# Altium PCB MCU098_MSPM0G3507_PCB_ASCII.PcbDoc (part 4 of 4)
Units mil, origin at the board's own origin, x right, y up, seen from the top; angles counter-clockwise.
Board outline 2310.03 x 4205.03 mil, 4 copper layers (Top Layer, VCC Layer, GND Layer, Bottom Layer), stack 62.4 mil thick; 260 components, 182 nets, 835 pads, 237 vias.
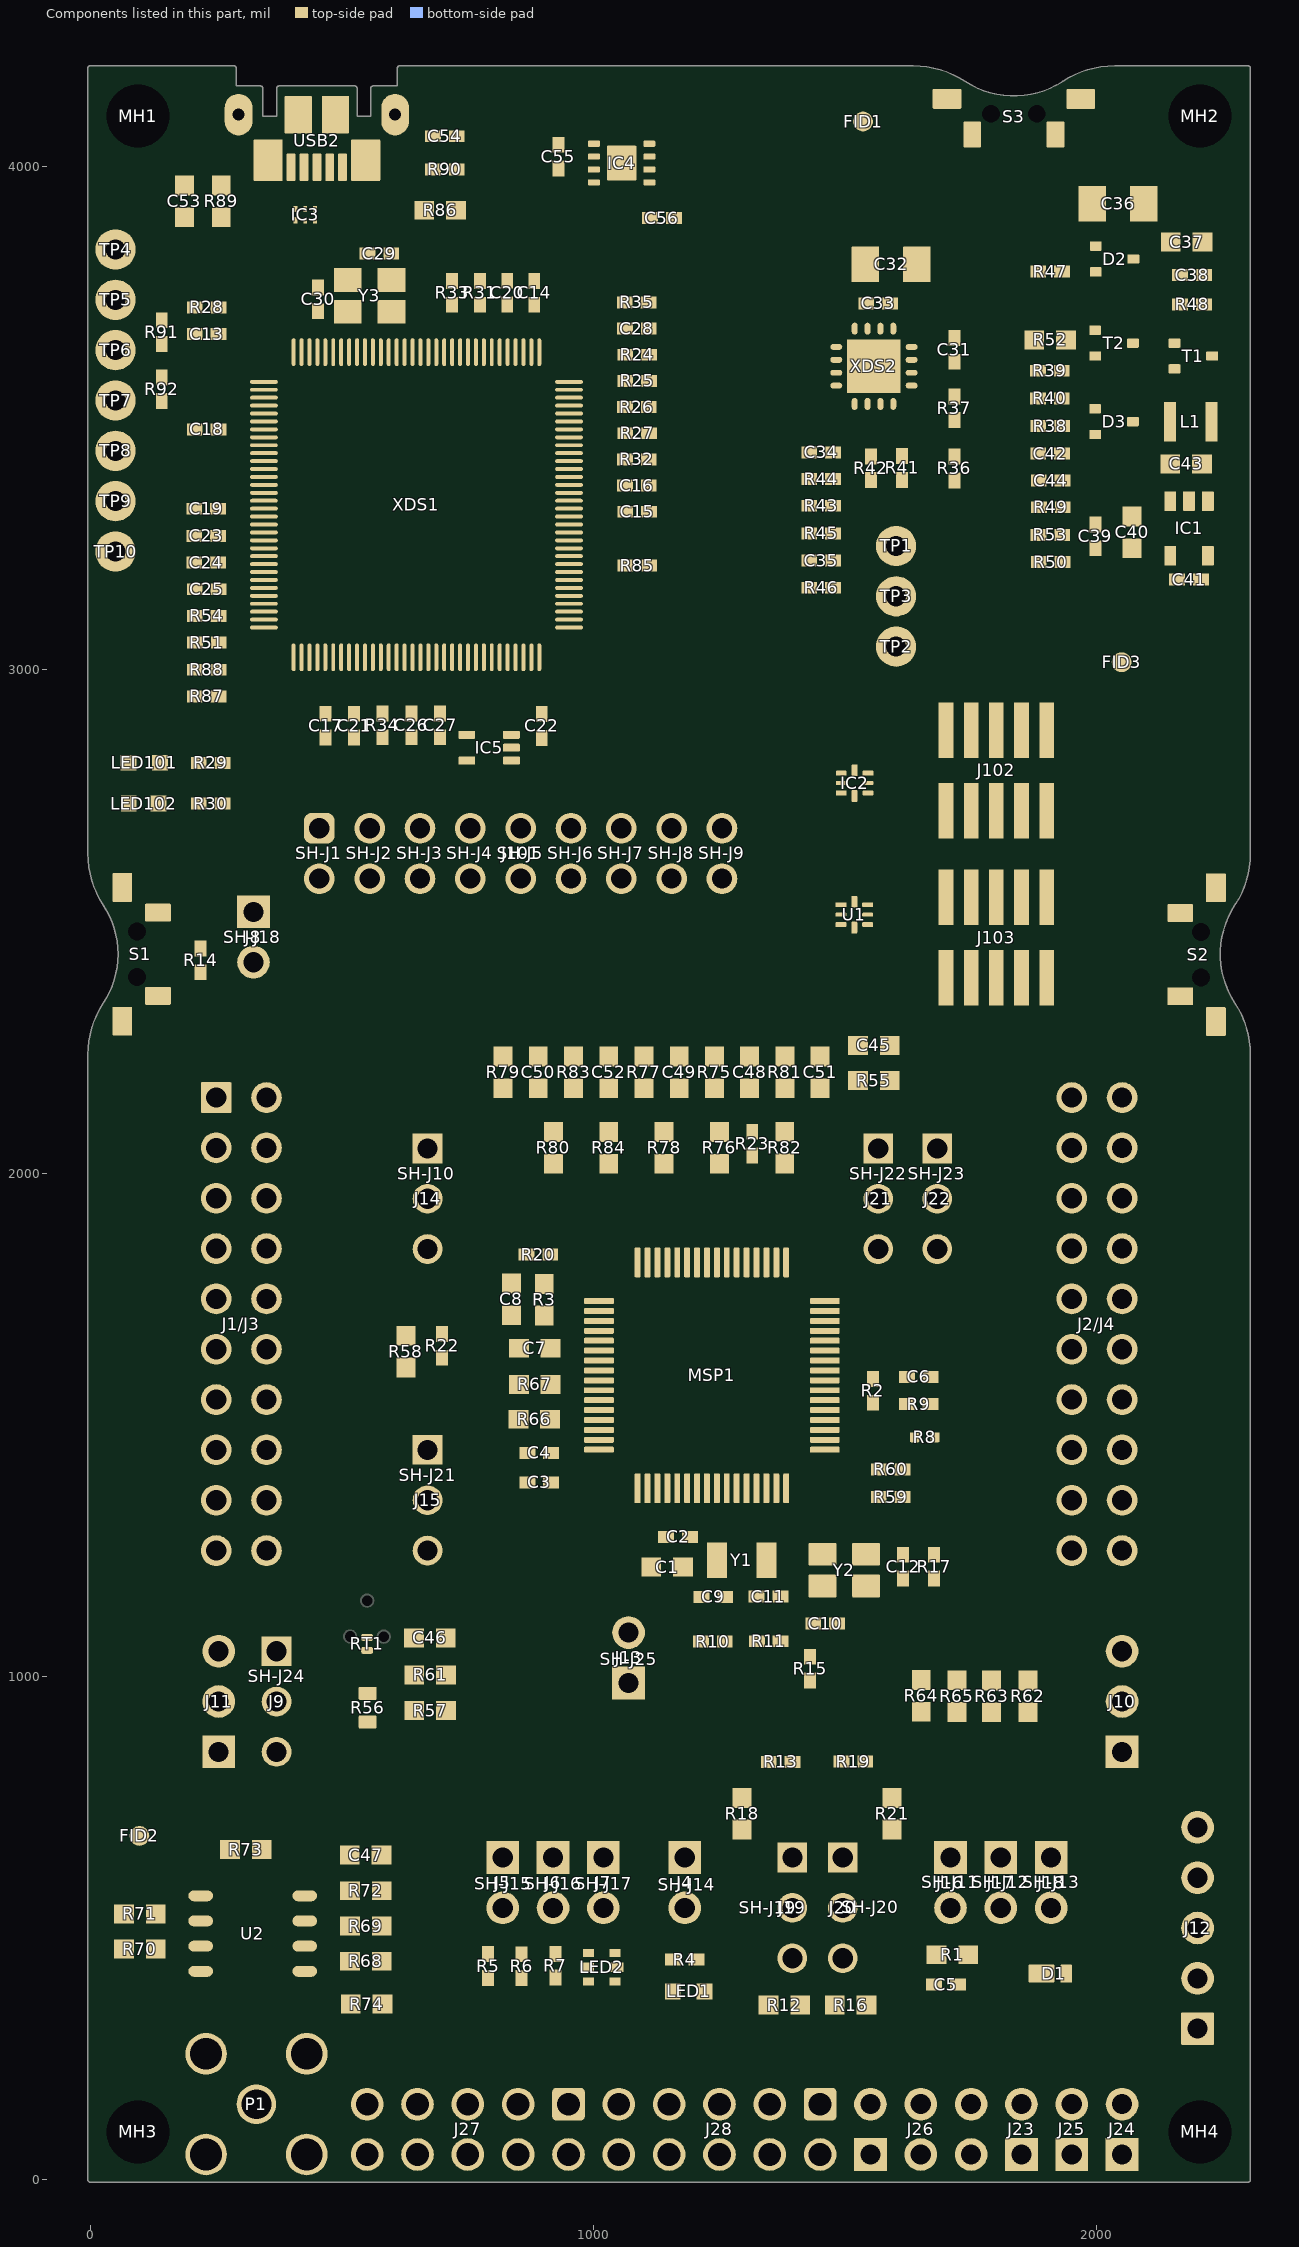
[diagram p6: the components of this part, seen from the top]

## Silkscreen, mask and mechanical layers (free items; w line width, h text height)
Top Overlay:
  drawing of 1933 lines, arcs and shapes, not listed
  text "MSP NRST" at 1606.35,3946.95 h40
  text "Rev. A" at 2264.13,2813.42 h50 r90
  text "XDS110-ET Debug Probe" at 428.03,2753 h30
  text "Rev1.4" at 1158,2747 h30
  text "XDS110 Out" at 1650.72,2668 h30 r90
  text "LP-MSPM0G3507" at 2205.15,2665.28 h65 r90
  text "(PB21)" at 1946.02,2381.37 h40
  text "BSL" at 1277.43,2376.37 h40 r90
  text "NRST" at 980,2358 h40 r90
  text "SWDIO" at 1074.13,2342 h40 r90
  text "SWCLK" at 1169.54,2342 h40 r90
  text "RXD<<" at 775,2340 h40 r90
  text "TXD>>" at 875,2340 h40 r90
  text "XDS110 In" at 1647,2340.5 h30 r90
  text "(PA18)" at 240.75,2280.75 h40
  text "PB4" at 1750,2130 h60
  text "PB4" at 1750.21,2130 h60
  text "XDS" at 1404.48,2031.35 h60
  text "PA25" at 50,2030 h60
  text "PB1" at 1750,2030 h60
  text "PB12" at 2160,2030 h60
  text "PB23" at 735.69,2027 h60
  text "SW1" at 50,1930 h60
  text "PB19" at 460,1930 h60
  text "PA28" at 1750,1930 h60
  text "PB17" at 2160,1930 h60
  text "SW1" at 751.47,1927.61 h60
  text "UART" at 1479.2,1899.56 h40 r90
  text "MSPM0G3507" at 1075.32,1867.37 h50
  text "BP" at 1440.73,1834.22 h60
  text "PA8" at 50,1830 h60
  text "PA22" at 460,1830 h60
  text "PA9" at 735,1830 h60
  text "PA31" at 1750,1830 h60
  text "PB15" at 2160,1830 h60
  text "PA26" at 50,1730 h60
  text "PB18" at 460,1730 h60
  text "PB20" at 1750,1730 h60
  text "NRST" at 2160,1730 h60
  text "PB24" at 50,1630 h60
  text "PA18" at 460,1630 h60
  text "PB13" at 1750,1630 h60
  text "PB8" at 2160,1630 h60
  text "PB9" at 50,1530 h60
  text "PA24" at 460,1530 h60
  text "PA10" at 1750,1530 h60
  text "PB7" at 2160,1530 h60
  text "PA27" at 50,1430 h60
  text "PA17" at 460,1430 h60
  text "PA11" at 1750,1430 h60
  text "PB6" at 2160,1430 h60
  text "PB2" at 50,1330 h60
  text "SW2" at 460,1330 h60
  text "PA12" at 1750,1330 h60
  text "PB0" at 2160,1330 h60
  text "PA16" at 818.4,1296 h60
  text "SW2" at 818,1238 h60
  text "PB3" at 50,1230 h60
  text "PA15" at 460,1230 h60
  text "PA13" at 1750,1230 h60
  text "PB16" at 2160,1230 h60
  text "PA18" at 819,1180 h60
  text "Thermistor" at 633.72,1110 h60
  text "PB24" at 467,993.43 h60 r90
  text "A.PWR" at 1005.13,939.83 h60 r90
  text "PA26" at 468.29,791 h60 r90
  text "PA22" at 1700.04,779.62 h60 r45
  text "PA27" at 1800,780 h60 r45
  text "PA26" at 1900,779 h60 r45
  text "PB22" at 786.74,775.84 h60 r45
  text "PA0" at 1160.62,775 h60 r45
  text "PB27" at 985.59,774 h60 r45
  text "PB26" at 887.2,773 h60 r45
  text "OPA2365" at 200,702.38 h60
  text "3V" at 1263.78,611 h60
  text "3V" at 1561.78,611 h60
  text "5V" at 1264.78,423.62 h60
  text "5V" at 1560.78,422.62 h60
  text "QEI Interface" at 2125.72,310.72 h80 r90
  text "B25" at 610,260 h50
  text "B11" at 809.84,260 h50
  text "B5" at 923.84,260 h50
  text "A14" at 1109.62,260 h50
  text "A6" at 1223,260 h50
  text "A4" at 1322,259.58 h50
  text "A2" at 1418,260 h50
  text "GND" at 1501,260.16 h50
  text "GND" at 1603.72,260.16 h50
  text "A11" at 1708,260 h50
  text "A0" at 522.4,258.56 h50
  text "B22" at 709.84,259 h50
  text "A1" at 1024,258.56 h50
  text "GND" at 2004,236 h50
  text "5V" at 1825.92,234 h50
  text "3V3" at 1908.5,234 h50
  text "B27" at 509.84,209.66 h50
  text "B26" at 609.84,209.66 h50
  text "B23" at 710,209.66 h50
  text "B21" at 810,210 h50
  text "B10" at 910,209.67 h50
  text "A23" at 1009.84,210 h50
  text "A21" at 1110.13,210 h50
  text "A7" at 1223,210 h50
  text "A5" at 1322,210 h50
  text "A3" at 1418,210 h50
  text "A12" at 1500,210 h50
  text "A13" at 1606.03,210 h50
  text "A10" at 1708,210 h50
  text ".Layer_Name" at 527,-1523.49 h30
Bottom Overlay:
  drawing of 24769 lines, arcs and shapes, not listed
  text "PB4" at 1868.21,2129.3 h60
  text "PA25" at 145.94,2030.07 h60
  text "PB1" at 1868,2029.3 h60
  text "PB12" at 2278,2029.3 h60
  text "SW1" at 145.94,1930.07 h60
  text "PB19" at 555.94,1930.07 h60
  text "PA28" at 1868,1929.3 h60
  text "PB17" at 2278,1929.3 h60
  text "PA8" at 145.94,1830.07 h60
  text "PA22" at 555.94,1830.07 h60
  text "PA31" at 1868,1829.3 h60
  text "PB15" at 2278,1829.3 h60
  text "PA26" at 145.94,1730 h60
  text "PB18" at 555.94,1730.07 h60
  text "PB20" at 1868,1729.3 h60
  text "NRST" at 2278,1729.3 h60
  text "PB24" at 145.94,1630 h60
  text "PA18" at 555.94,1630.07 h60
  text "PB13" at 1868,1629.3 h60
  text "PB8" at 2278,1629.3 h60
  text "PB9" at 145.94,1530.07 h60
  text "PA24" at 555.94,1530.07 h60
  text "PA10" at 1868,1529.3 h60
  text "PB7" at 2278,1529.3 h60
  text "PA27" at 145.94,1430.07 h60
  text "PA17" at 555.94,1430.07 h60
  text "PA11" at 1868,1429.3 h60
  text "PB6" at 2278,1429.3 h60
  text "PB2" at 145.94,1330.07 h60
  text "SW2" at 555.94,1330.07 h60
  text "PA12" at 1868,1329.3 h60
  text "PB0" at 2278,1329.3 h60
  text "PB3" at 145.94,1230.07 h60
  text "PA15" at 555.94,1230.07 h60
  text "PA13" at 1868,1229.3 h60
  text "PB16" at 2278,1229.3 h60
  text "GND" at 2128,682.97 h60
  text "3V3" at 2128,582.97 h60
  text "PB14" at 2128,481.97 h60
  text "PA30" at 2128,382.97 h60
  text "PA29" at 2128,282.97 h60
  text ".Layer_Name" at 527,-1523.49 h30
Top Paste:
  text ".Layer_Name" at 527,-1523.49 h30
Bottom Paste:
  text ".Layer_Name" at 527,-1523.49 h30
Top Solder:
  text ".Layer_Name" at 527,-1523.49 h30
  text ".Layer_Name" at 527,-1523.49 h30
Bottom Solder:
  text ".Layer_Name" at 527,-1523.49 h30
Drill Guide:
  text ".Layer_Name" at 527,-1523.49 h30
M1 Board Outline:
  lines w10: 0,0 0,2235 ; 0,0 2300,0 ; 0,0 2300,0 ; 0,0 0,2235 ; 0,2235 cw(c181.67,2235) 30,2335 ; 0,2235 cw(c181.67,2235) 30,2335 ; 0,2635 ccw(c181.67,2635) 30,2535 ; 0,2635 ccw(c181.67,2635) 30,2535 ; 0,2635 0,4195 ; 0,2635 0,4195 ; 0,4195 285,4195 ; 0,4195 285,4195 ; 30,2335 ccw(c-121.67,2435) 30,2535 ; 30,2335 ccw(c-121.67,2435) 30,2535 ; 30,2535 30,2535 ; 285,4155 338,4155 ; 285,4155 285,4195 ; 285,4155 285,4195 ; 285,4155 338,4155 ; 338,4095 375,4095 ; 338,4095 338,4155 ; 338,4095 338,4155 ; 338,4095 375,4095 ; 375,4095 375,4155 ; 375,4095 375,4155 ; 375,4155 525,4155 ; 375,4155 525,4155 ; 525,4095 562,4095 ; 525,4095 525,4155 ; 525,4095 525,4155 ; 525,4095 562,4095 ; 562,4095 562,4155 ; 562,4095 562,4155 ; 562,4155 615,4155 ; 562,4155 615,4155 ; 615,4155 615,4195 ; 615,4155 615,4195 ; 615,4195 1635,4195 ; 615,4195 1635,4195 ; 1635,4195 cw(c1635,4013.33) 1735,4165 ; 1635,4195 cw(c1635,4013.33) 1735,4165 ; 1735,4165 ccw(c1835,4316.67) 1935,4165 ; 1735,4165 ccw(c1835,4316.67) 1935,4165 ; 1935,4165 cw(c2035,4013.33) 2035,4195 ; 1935,4165 cw(c2035,4013.33) 2035,4195 ; 1935,4165 1935,4165 ; 2035,4195 2300,4195 ; 2035,4195 2300,4195 ; 2270,2335 cw(c2118.33,2235) 2300,2235 ; 2270,2335 cw(c2421.67,2435) 2270,2535 ; 2270,2335 cw(c2421.67,2435) 2270,2535 ; 2270,2335 cw(c2118.33,2235) 2300,2235 ; 2270,2335 2270,2335 ; 2270,2535 ccw(c2118.33,2635) 2300,2635 ; 2270,2535 ccw(c2118.33,2635) 2300,2635 ; 2300,0 2300,2235 ; 2300,0 2300,2235 ; 2300,2635 2300,4195 ; 2300,2635 2300,4195
  text ".Layer_Name" at 527,-1523.49 h30
M2 Board Dimensions:
  rectangle: 75,-1065 450,-940
  rectangle: -50,-940 75,-815
  lines w7: -50,-940 950,-940 ; 75,-1065 75,-815 ; 200,-1065 200,-815 ; 450,-1065 450,-815 ; 700,-1065 700,-815 ; -50,-1065 -50,-815 950,-815 950,-1065 -50,-1065
  lines w10: 1711,4198.98 1711,4256.98 1917,4462.98 1987.5,4462.98 ; 1835,4160.98 1835,4278.98 1919,4362.98 1995,4362.98 ; 1955,4198.98 1955,4252.98 1980,4277.98 1995,4277.98 ; 1980,4462.98 1995,4462.98 ; 2350,4197.98 2375,4222.98 2375,4512.98 2350,4537.98
  text "Radius 180" at 2015,4437.98 h30
  text "Radius 180" at 2015,4342.98 h30
  text "3 Places" at 2450,4340 h30
  text "Radius 180" at 2015,4252.98 h30
  text ".Layer_Name" at 527,-1523.49 h30
M3 3D STEP Top:
  text ".Layer_Name" at 527,-1523.49 h30
M4 3D STEP Bottom:
  text ".Layer_Name" at 527,-1523.49 h30
M5 Assembly Top:
  circle w6: c1382.04,1872 r5.83
  lines w10: -342,-1595.17 6258,-1595.17 ; -342,-1391.83 6260,-1391.83 ; -342,-1188.5 -342,-1798.5 3663,-1798.5 6260,-1798.5 6260,-1188.5 -341.5,-1188.5 -341.5,-1798.5 1234,-1798.5 ; 2123,-1798.5 2123,-1188.5 ; 3390,-1391.83 3390,-1188.5 ; 4230,-1391.83 4230,-1188.5 ; 4852,-1805 4852,-1602.17
  text "COMPONENTS MARKED 'DNP' SHOULD NOT BE POPULATED." at 1103.5,-983.5 h30
  text "ASSEMBLY VARIANT:" at 1103,-1099 h30
  text ".VariantName" at 2139,-1099 h30
  text "PCB VIEWED FROM TOP SIDE" at -278.5,-1320.67 h30
  text "BOARD #:" at 2198,-1320.67 h30
  text ".PRJ_Number" at 2743.5,-1320.67 h30
  text "REV:" at 3588,-1320.67 h30
  text ".PCB_Rev" at 3879.5,-1320.67 h30
  text "SVN REV:" at 4426,-1320.67 h30
  text ".VersionControl_RevNumber" at 4932,-1320.67 h30
  text "TID #:" at 2198,-1524 h30
  text ".TID" at 2743.5,-1524 h30
  text "PLOT NAME =" at -278.5,-1729.34 h30
  text ".plot_File_Name" at 527,-1729.34 h30
  text "GENERATED    :" at 2200,-1729.34 h30
  text ".Print_Date" at 3069.5,-1729.34 h30
  text ".Print_Time" at 3798.5,-1729.34 h30
  text "TEXAS INSTRUMENTS" at 5063,-1729.34 h30
M6 Assembly Bottom:
  lines w10: -342.5,-1392.33 6259.5,-1392.33 ; -340.5,-1595.67 6259.5,-1595.67 ; 1065.5,-1805.5 1065.5,-1602.67 ; 1687.5,-1392.33 1687.5,-1189 ; 2527.5,-1392.33 2527.5,-1189 ; 3794.5,-1799 3794.5,-1189 ; 4683.5,-1799 6259,-1799 6259,-1189 -342.5,-1189 -342.5,-1799 2254.5,-1799 6259.5,-1799 6259.5,-1189
  text "COMPONENTS MARKED 'DNP' SHOULD NOT BE POPULATED." at 6052,-983 h30
  text ".VariantName" at 5008,-1099 h30
  text "ASSEMBLY VARIANT:" at 6047,-1099 h30
  text ".VersionControl_RevNumber" at 985.5,-1321.17 h30
  text "SVN REV:" at 1491.5,-1321.17 h30
  text ".PCB_Rev" at 2038,-1321.17 h30
  text "REV:" at 2329.5,-1321.17 h30
  text ".PRJ_Number" at 3174,-1321.17 h30
  text "BOARD #:" at 3719.5,-1321.17 h30
  text "PCB VIEWED FROM BOTTOM SIDE" at 6196,-1321.17 h30
  text ".TID" at 3174,-1524.5 h30
  text "TID #:" at 3719.5,-1524.5 h30
  text "TEXAS INSTRUMENTS" at 854.5,-1729.84 h30
  text ".Print_Time" at 2119,-1729.84 h30
  text ".Print_Date" at 2848,-1729.84 h30
  text "GENERATED    :" at 3717.5,-1729.84 h30
  text ".plot_File_Name" at 5390.5,-1729.84 h30
  text "PLOT NAME =" at 6196,-1729.84 h30
M9 Title Sheet:
  lines w10: -541.5,376.5 -341.5,376.5 ; -541.5,2751.5 -341.5,2751.5 ; -541.5,5126.5 -341.5,5126.5 ; 1958.5,-1998.5 1958.5,-1798.5 ; 1958.5,7301.5 1958.5,7501.5 ; 4458.5,-1998.5 4458.5,-1798.5 ; 4458.5,7301.5 4458.5,7501.5 ; 6271,-1798.5 6271,-1188.5 11253.5,-1188.5 ; 6958.5,-1998.5 6958.5,-1798.5 ; 6958.5,7301.5 6958.5,7501.5 ; 9458.5,-1998.5 9458.5,-1798.5 ; 9458.5,7301.5 9458.5,7501.5 ; 11253.5,-1798.5 11253.5,-1188.5 ; 11253.5,-1488.5 14253.5,-1488.5 ; 11253.5,-888.5 14253.5,-888.5 ; 11254.5,-294.5 14254.5,-294.5 ; 11958.5,-1998.5 11958.5,-1798.5 ; 11958.5,7301.5 11958.5,7501.5 ; 12758.5,-1788.5 12758.5,-1188.5 ; 14253.5,-1188.5 11253.5,-1188.5 ; 14253.5,-588.5 11253.5,-588.5 ; 14258.5,-598.5 14258.5,-1798.5 ; 14258.5,206 11254.5,206 11253.5,206 11253.5,-294.5 11253.5,-588.5 ; 14258.5,376.5 14458.5,376.5 ; 14258.5,2751.5 14458.5,2751.5 ; 14258.5,5126.5 14458.5,5126.5 ; 11253.5,-1188.5 11253.5,-588.5 ; 14258.5,-1798.5 -341.5,-1798.5 -341.5,7301.5 14258.5,7301.5 14258.5,-1798.5 ; -541.5,-1998.5 14458.5,-1998.5 14458.5,7501.5 -541.5,7501.5 -541.5,-1998.5
  text "1" at 689.84,7371.5 h30
  text "2" at 3185.5,7371.5 h30
  text "3" at 5674.84,7371.5 h30
  text "4" at 8181.51,7371.5 h30
  text "5" at 10680.5,7371.5 h30
  text "6" at 13185.5,7371.5 h30
  text "A" at -466.5,6228.5 h30
  text "A" at 14333.5,6228.5 h30
  text "B" at -466.5,3848.5 h30
  text "B" at 14333.5,3848.5 h30
  text "C" at -466.5,1473.5 h30
  text "C" at 14333.5,1473.5 h30
  text "PROJECT TITLE:" at 11293.5,-387.5 h30
  text ".PRJ_Title" at 11343.5,-520.83 h30
  text "DESIGNED FOR:" at 11293.5,-688.5 h30
  text ".PRJ_Customer" at 11343.5,-828.5 h30
  text "D" at -466.5,-896.5 h30
  text "D" at 14333.5,-896.5 h30
  text "FILE NAME:" at 11293.5,-988.5 h30
  text ".PCB_File_Name_No_Path" at 11343.5,-1108.5 h30
  text "Texas Instruments (TI) and/or its licensors do not warrant the accuracy or completeness of this specification" at 6324,-1270.34 h30
  text "ENGINEER:" at 11293.5,-1278.5 h30
  text "LAYOUT BY:" at 12798.5,-1278.5 h30
  text "or any information contained therein. TI and/or its licensors do not warrant that this design will meet" at 6279.01,-1383 h30
  text ".PRJ_Engineer" at 11343.5,-1433.49 h30
  text ".PCB_Layout" at 12849,-1433.49 h30
  text "the specifications, will be suitable for your application or fit for any particular purpose, or will operate in" at 6279.01,-1495.67 h30
  text ".Layer_Name" at 527,-1523.49 h30
  text "ALTIUM DESIGNER VERSION:" at 12798.5,-1588.5 h30
  text "an implementation. TI and/or its licensors do not warrant that the design is production worthy. You should" at 6279.01,-1608.33 h30
  text "completely validate and test your design implementation to confirm the system functionality for your application." at 6324,-1721 h30
  text ".print_Scale" at 11343.5,-1721.83 h30
  text ".Application_BuildNumber" at 12849,-1721.83 h30
  text "1" at 689.84,-1928.5 h30
  text "2" at 3185.5,-1928.5 h30
  text "3" at 5674.84,-1928.5 h30
  text "4" at 8181.51,-1928.5 h30
  text "5" at 10680.5,-1928.5 h30
  text "6" at 13185.5,-1928.5 h30
M10 Fab Notes:
  drawing of 173 lines, arcs and shapes, not listed
  text "DESIGN INFORMATION" at 12328.02,5536 h30
  text "MIN. TRACK WIDTH:" at 11683.46,5356 h30
  text "8" at 12779.7,5356 h30
  text "MIL" at 12934.46,5356 h30
  text "MIN. CLEARANCE:" at 11683.46,5224 h30
  text "0.2" at 12719.7,5224 h30
  text "mm" at 12934.46,5224 h30
  text "MIN. VIA PAD SIZE:" at 11683.46,5092 h30
  text "24" at 12749.71,5092 h30
  text "MIL" at 12934.46,5092 h30
  text "0.05mm (2MIL)" at 12378.46,4950.29 h30
  text "MINIMUM ANNULAR RING" at 11354.23,4946 h30
  text "EXTERNAL" at 13086.46,4946 h30
  text "PER" at 11554.23,4828 h30
  text "IPC-D-275 CLASS 2 LEVEL C" at 11774.23,4828 h30
  text "MIL, HOLES" at 13262.46,4715.71 h30
  text "+/-" at 12870,4715 h30
  text "+/-" at 13724,4715 h30
  text "REGISTRATION TOLERANCES:" at 11354.23,4710 h30
  text "METAL" at 12554,4710 h30
  text "5" at 13130.2,4710 h30
  text "3" at 13963.2,4710 h30
  text "MIL" at 14079.46,4710 h30
  text "+/-" at 13724,4597 h30
  text "HOLE SIZE TOLERANCE (UNLESS OTHERWISE SPECIFIED):" at 11354.23,4592 h30
  text "3" at 13963.2,4592 h30
  text "MIL" at 14079.46,4592 h30
  text "MATERIAL:" at 11279.46,4382.54 h30
  text "FR-4 High Tg" at 12265.9,4242.21 h30
  text "FR-408" at 11700.46,4233.64 h30
  text "OTHER" at 13188.46,4233.64 h30
  text "X" at 12111,4230 h30
  text "62 MIL (1.6mm) +/-10%" at 12020.56,4070.92 h30
  text "THICKNESS:" at 11354.23,4066.64 h30
  text "X" at 11892.4,4066.64 h30
  text "OTHER" at 13305.46,4066.64 h30
  text "TOLERANCE:" at 11354.23,3908.64 h30
  text "X" at 12193.53,3908.64 h30
  text "ANSI IPC-6012 TYPE 3 CLASS 2" at 12380.48,3908.64 h30
  text "OTHER +/-" at 12380.46,3752.64 h30
  text "BOW & TWIST:" at 11354.23,3595.64 h30
  text "X" at 12193.53,3595.64 h30
  text "ANSI IPC-6012 TYPE 3 CLASS 2" at 12380.48,3595.64 h30
  text "OTHER +/-" at 12380.46,3437.13 h30
  text "DRILLING:" at 11279.46,3298.64 h30
  text "REFERENCE:" at 11354.23,3181.64 h30
  text "X" at 12002.46,3181.64 h30
  text "AS SHOWN" at 12189.46,3181.64 h30
  text "X" at 12903.46,3181.64 h30
  text "NC_DRILL FILES" at 13040.46,3181.64 h30
  text "PTH COPPER THICKNESS:" at 11354.23,3023.64 h30
  text "X" at 12484.46,3023.64 h30
  text "20-30 um" at 12621.46,3023.64 h30
  text "OTHER" at 13338.46,3023.64 h30
  text "BOARD FINISH:" at 11279.46,2864.64 h30
  text "SILKSCREEN:" at 11434.68,2746.64 h30
  text "X" at 12383.46,2746.64 h30
  text "TOP" at 12509.46,2746.64 h30
  text "X" at 12893.46,2746.64 h30
  text "BOTTOM" at 13020.46,2746.64 h30
  text "SILKSCREEN COLOR:" at 11434.68,2579.64 h30
  text "X" at 12382.42,2579.64 h30
  text "WHITE" at 12509.46,2579.64 h30
  text "OTHER" at 13020.46,2579.64 h30
  text "GREEN" at 12640.46,2420.44 h30
  text "X" at 13105,2420 h30
  text "OTHER" at 13258.46,2420.44 h30
  text "Red" at 13655,2420 h30
  text "SOLDER RESIST COLOR:" at 11434.68,2409.64 h30
  text "X" at 12513.42,2250.44 h30
  text "MATTE" at 12640.46,2250.44 h30
  text "SEMI-GLOSS" at 13258,2249.8 h30
  text "IMMERSION GOLD (ENIG)" at 12340.46,2061.92 h30
  text "ENEPIG" at 13678,2058.64 h30
  text "SURFACE FINISH:" at 11279.46,2057.64 h30
  text "IMM. TIN/SILVER OR EQUIV" at 11609,1900.64 h30
  text "OTHER" at 13040.46,1900.64 h30
  text "X" at 11445,1900 h30
  text "ARRAY/PANEL:" at 11279.46,1721.64 h30
  text "CUT AND TRIM PER M1 BOARD OUTLINE" at 12340.46,1717.35 h30
  text "N.C. ROUTE" at 12340.46,1565.64 h30
  text "X" at 13019.46,1565.64 h30
  text "V. SCORE" at 13206.46,1565.64 h30
  text "CERTIFICATION:" at 11279.46,1428.64 h30
  text "MATERIALS AND WORKMANSHIP FOR ALL PCBS" at 12004.46,1428.64 h30
  text "TO MEET OR EXCEED THE REQUIREMENTS OF:" at 12004.46,1330.64 h30
  text "X" at 11630.96,1194.13 h30
  text "ANSI IPC-A-600F CLASS ->" at 11769.96,1194.13 h30
  text "X" at 13409.02,1194.13 h30
  text "2" at 13527.96,1194.14 h30
  text "1" at 13212.96,1192.64 h30
  text "3" at 13881.96,1192.64 h30
  text "X" at 12445.02,1034.64 h30
  text "RoHS" at 12581.96,1034.64 h30
  text "OTHER" at 13226.36,1034.64 h30
  text "PER ORDER" at 13623.42,1034.64 h30
  text "ALL BOARDS MUST MEET OR EXCEED UL94-V0 REQUIREMENTS." at 11307,869 h30
  text "PCB MUST BEAR THE UL94V-0 UL REGISTERED MATERIAL ID NUMBER" at 11307,749 h30
  text "ADDITIONAL REQUIREMENTS:" at 11279.46,575.64 h30
  text "MICROSECTION:" at 11354.23,460.64 h30
  text "YES" at 12259.96,460.64 h30
  text "X" at 13585,305 h30
  text "REQUIRED" at 13121.46,304.49 h30
  text "BARE BOARD ELEC. TEST:" at 11354.23,301.64 h30
  text "NONE" at 12659.96,301.64 h30
  text "PER ORDER" at 13713.46,301.64 h30
  text ".Layer_Name" at 527,-1523.49 h30
M11 Gerber Information:
  lines w10: -342,-1595.17 6258,-1595.17 ; -342,-1391.83 6260,-1391.83 ; -342,-1188.5 -342,-1798.5 3663,-1798.5 6260,-1798.5 6260,-1188.5 -341.5,-1188.5 -341.5,-1798.5 1234,-1798.5 ; 2123,-1798.5 2123,-1188.5 ; 3390,-1391.83 3390,-1188.5 ; 4230,-1391.83 4230,-1188.5 ; 4852,-1805 4852,-1602.17
  text "ALL ARTWORK VIEWED FROM TOP SIDE" at -278.5,-1320.67 h30
  text "BOARD #:" at 2198,-1320.67 h30
  text ".PRJ_Number" at 2743.5,-1320.67 h30
  text "REV:" at 3588,-1320.67 h30
  text ".PCB_Rev" at 3879.5,-1320.67 h30
  text "SVN REV:" at 4426,-1320.67 h30
  text ".VersionControl_RevNumber" at 4932,-1320.67 h30
  text "LAYER NAME =" at -278.5,-1523.49 h30
  text "TID #:" at 2198,-1524 h30
  text ".TID" at 2743.5,-1524 h30
  text "PLOT NAME =" at -278.5,-1729.34 h30
  text ".plot_File_Name" at 527,-1729.34 h30
  text "GENERATED    :" at 2200,-1729.34 h30
  text ".Print_Date" at 3069.5,-1729.34 h30
  text ".Print_Time" at 3798.5,-1729.34 h30
  text "TEXAS INSTRUMENTS" at 5063,-1729.34 h30
M12 Stackup:
  drawing of 295 lines, arcs and shapes, not listed
  text "Layer" at 8601.29,5576 h30
  text "Name" at 8816.24,5576 h30
  text "Material" at 9291.12,5576 h30
  text "Thickness" at 9581.05,5576 h30
  text "Constant" at 9915.97,5576 h30
  text "Board Layer Stack" at 10210.9,5576 h30
  text "Top Overlay" at 8816.24,5516 h30
  text "Top Solder" at 8816.24,5456 h30
  text "SM-004" at 9291.12,5456 h30
  text "0.98mil" at 9581.05,5456 h30
  text "4" at 9915.97,5456 h30
  text "1" at 8601.29,5396 h30
  text "Top Layer" at 8816.24,5396 h30
  text "1.40mil" at 9581.05,5396 h30
  text "Dielectric 2" at 8816.24,5336 h30
  text "FR-4" at 9291.12,5336 h30
  text "8.40mil" at 9581.05,5336 h30
  text "4.2" at 9915.97,5336 h30
  text "2" at 8601.29,5276 h30
  text "VCC Layer" at 8816.24,5276 h30
  text "1.40mil" at 9581.05,5276 h30
  text "Dielectric1" at 8816.24,5216 h30
  text "FR-4" at 9291.12,5216 h30
  text "40.00mil" at 9581.05,5216 h30
  text "4.2" at 9915.97,5216 h30
  text "3" at 8601.29,5156 h30
  text "GND Layer" at 8816.24,5156 h30
  text "1.40mil" at 9581.05,5156 h30
  text "Dielectric 3" at 8816.24,5096 h30
  text "FR-4" at 9291.12,5096 h30
  text "8.40mil" at 9581.05,5096 h30
  text "4.2" at 9915.97,5096 h30
  text "4" at 8601.29,5036 h30
  text "Bottom Layer" at 8816.24,5036 h30
  text "1.40mil" at 9581.05,5036 h30
  text "Bottom Solder" at 8816.24,4976 h30
  text "SM-004" at 9291.12,4976 h30
  text "0.98mil" at 9581.05,4976 h30
  text "4" at 9915.97,4976 h30
  text "Bottom Overlay" at 8816.24,4916 h30
  text ".Layer_Name" at 527,-1523.49 h30
M13 Component Bodies Top:
  text ".Layer_Name" at 527,-1523.49 h30
M14 Component Bodies Bottom:
  text ".Layer_Name" at 527,-1523.49 h30
M15 Courtyards Top:
  text ".Layer_Name" at 527,-1523.49 h30
M16 Courtyards Bottom:
  text ".Layer_Name" at 527,-1523.49 h30
Drill Drawing:
  circle w10: c6074.13,4457.29 r10
  circle w10: c6074.13,4457.29 r16.67
  circle w10: c6074.13,3707.29 r16.67
  lines w10: 6057.46,3765.62 6074.13,3773.96 6090.79,3765.62 6082.46,3782.29 6090.79,3798.96 6074.13,3790.62 6057.46,3798.96 6065.79,3782.29 6057.46,3765.62 ; 6057.46,3840.62 6090.79,3840.62 6090.79,3873.96 6057.46,3873.96 6057.46,3840.62 ; 6057.46,3915.62 6057.46,3923.96 6065.79,3932.29 6057.46,3940.62 6057.46,3948.96 6065.79,3948.96 6074.13,3940.62 6082.46,3948.96 6090.79,3948.96 6090.79,3940.62 6082.46,3932.29 6090.79,3923.96 6090.79,3915.62 6082.46,3915.62 6074.13,3923.96 6065.79,3915.62 6057.46,3915.62 ; 6057.46,4007.29 6074.13,3990.62 6090.79,4007.29 6074.13,4023.96 6057.46,4007.29 ; 6057.46,4073.96 6065.79,4073.96 6065.79,4065.62 6082.46,4065.62 6082.46,4073.96 6090.79,4073.96 6090.79,4090.62 6082.46,4090.62 6082.46,4098.96 6065.79,4098.96 6065.79,4090.62 6057.46,4090.62 6057.46,4073.96 ; 6057.46,4140.62 6074.13,4148.96 6090.79,4140.62 6082.46,4157.29 6090.79,4173.96 6074.13,4165.62 6057.46,4173.96 6065.79,4157.29 6057.46,4140.62 ; 6057.46,4248.96 6090.79,4248.96 6074.13,4215.62 6057.46,4248.96 ; 6057.46,4323.96 6090.79,4323.96 6074.13,4290.62 6057.46,4323.96 ; 6057.46,4373.96 6065.79,4373.96 6074.13,4365.62 6082.46,4373.96 6090.79,4373.96 6082.46,4382.29 6090.79,4390.62 6082.46,4390.62 6074.13,4398.96 6065.79,4390.62 6057.46,4390.62 6065.79,4382.29 6057.46,4373.96 ; 6057.46,4515.62 6057.46,4523.96 6065.79,4532.29 6057.46,4540.62 6057.46,4548.96 6065.79,4548.96 6074.13,4540.62 6082.46,4548.96 6090.79,4548.96 6090.79,4540.62 6082.46,4532.29 6090.79,4523.96 6090.79,4515.62 6082.46,4515.62 6074.13,4523.96 6065.79,4515.62 6057.46,4515.62 ; 6057.46,4590.62 6090.79,4590.62 6090.79,4623.96 6057.46,4623.96 6057.46,4590.62 ; 6064.13,3772.29 6074.13,3777.29 6084.13,3772.29 6079.13,3782.29 6084.13,3792.29 6074.13,3787.29 6064.13,3792.29 6069.13,3782.29 6064.13,3772.29 ; 6064.13,4317.29 6084.13,4317.29 6074.13,4297.29 6064.13,4317.29 ; 6064.13,4377.29 6069.13,4377.29 6074.13,4372.29 6079.13,4377.29 6084.13,4377.29 6079.13,4382.29 6084.13,4387.29 6079.13,4387.29 6074.13,4392.29 6069.13,4387.29 6064.13,4387.29 6069.13,4382.29 6064.13,4377.29 ; 6064.13,4522.29 6064.13,4527.29 6069.13,4532.29 6064.13,4537.29 6064.13,4542.29 6069.13,4542.29 6074.13,4537.29 6079.13,4542.29 6084.13,4542.29 6084.13,4537.29 6079.13,4532.29 6084.13,4527.29 6084.13,4522.29 6079.13,4522.29 6074.13,4527.29 6069.13,4522.29 6064.13,4522.29 ; 6064.13,4597.29 6084.13,4597.29 6084.13,4617.29 6064.13,4617.29 6064.13,4597.29
  lines w12: 6026,3668.12 9906.95,3668.12 ; 6026,4643.12 9906.95,4643.12 ; 6317.44,3593.12 6317.44,4718.12 ; 6652.35,3593.12 6652.35,4718.12 ; 7341.16,3593.12 7341.16,4718.12 ; 7610.1,3593.12 7610.1,4718.12 ; 7993,3593.12 7993,4718.12 ; 8752.77,3593.12 8752.77,4718.12 ; 9309.62,3593.12 9309.62,4718.12 ; 6026,3593.12 9906.95,3593.12 9906.95,4718.12 6026,4718.12 6026,3593.12
  text "Symbol" at 6071,4665.62 h36
  text "Quantity" at 6339.94,4665.62 h36
  text "Finished Hole Size" at 6674.85,4665.62 h36
  text "Plated" at 7363.66,4665.62 h36
  text "Hole Type" at 7632.6,4665.62 h36
  text "Drill Layer Pair" at 8015.5,4665.62 h36
  text "Hole Tolerance" at 8775.27,4665.62 h36
  text "Hole Length" at 9332.12,4665.62 h36
  text "6" at 6339.94,4590.62 h30
  text "35.43mil (0.900mm)" at 6674.85,4590.62 h30
  text "NPTH" at 7363.66,4590.62 h30
  text "Round" at 7632.6,4590.62 h30
  text "Top Layer - Bottom Layer" at 8015.5,4590.62 h30
  text "-" at 9332.12,4590.62 h30
  text "4" at 6339.94,4515.62 h30
  text "125.00mil (3.175mm)" at 6674.85,4515.62 h30
  text "NPTH" at 7363.66,4515.62 h30
  text "Round" at 7632.6,4515.62 h30
  text "Top Layer - Bottom Layer" at 8015.5,4515.62 h30
  text "-" at 9332.12,4515.62 h30
  text "9" at 6339.94,4440.62 h30
  text "7.87mil (0.200mm)" at 6674.85,4440.62 h30
  text "PTH" at 7363.66,4440.62 h30
  text "Round" at 7632.6,4440.62 h30
  text "Top Layer - Bottom Layer" at 8015.5,4440.62 h30
  text "-" at 9332.12,4440.62 h30
  text "211" at 6339.94,4365.62 h30
  text "12.00mil (0.305mm)" at 6674.85,4365.62 h30
  text "PTH" at 7363.66,4365.62 h30
  text "Round" at 7632.6,4365.62 h30
  text "Top Layer - Bottom Layer" at 8015.5,4365.62 h30
  text "-" at 9332.12,4365.62 h30
  text "17" at 6339.94,4290.62 h30
  text "20.00mil (0.508mm)" at 6674.85,4290.62 h30
  text "PTH" at 7363.66,4290.62 h30
  text "Round" at 7632.6,4290.62 h30
  text "Top Layer - Bottom Layer" at 8015.5,4290.62 h30
  text "-" at 9332.12,4290.62 h30
  text "72" at 6339.94,4215.62 h30
  text "40.00mil (1.016mm)" at 6674.85,4215.62 h30
  text "PTH" at 7363.66,4215.62 h30
  text "Round" at 7632.6,4215.62 h30
  text "Top Layer - Bottom Layer" at 8015.5,4215.62 h30
  text "-" at 9332.12,4215.62 h30
  text "58" at 6339.94,4140.62 h30
  text "40.16mil (1.020mm)" at 6674.85,4140.62 h30
  text "PTH" at 7363.66,4140.62 h30
  text "Round" at 7632.6,4140.62 h30
  text "Top Layer - Bottom Layer" at 8015.5,4140.62 h30
  text "-" at 9332.12,4140.62 h30
  text "20" at 6339.94,4065.62 h30
  text "45.28mil (1.150mm)" at 6674.85,4065.62 h30
  text "PTH" at 7363.66,4065.62 h30
  text "Round" at 7632.6,4065.62 h30
  text "Top Layer - Bottom Layer" at 8015.5,4065.62 h30
  text "-" at 9332.12,4065.62 h30
  text "1" at 6339.94,3990.62 h30
  text "59.06mil (1.500mm)" at 6674.85,3990.62 h30
  text "PTH" at 7363.66,3990.62 h30
  text "Round" at 7632.6,3990.62 h30
  text "Top Layer - Bottom Layer" at 8015.5,3990.62 h30
  text "-" at 9332.12,3990.62 h30
  text "4" at 6339.94,3915.62 h30
  text "62.99mil (1.600mm)" at 6674.85,3915.62 h30
  text "PTH" at 7363.66,3915.62 h30
  text "Round" at 7632.6,3915.62 h30
  text "Top Layer - Bottom Layer" at 8015.5,3915.62 h30
  text "-" at 9332.12,3915.62 h30
  text "1" at 6339.94,3840.62 h30
  text "21.00mil (0.533mm)" at 6674.85,3840.62 h30
  text "NPTH" at 7363.66,3840.62 h30
  text "Slot" at 7632.6,3840.62 h30
  text "Top Layer - Bottom Layer" at 8015.5,3840.62 h30
  text "87.00mil (2.210mm)" at 9332.12,3840.62 h30
  text "2" at 6339.94,3765.62 h30
  text "21.00mil (0.533mm)" at 6674.85,3765.62 h30
  text "NPTH" at 7363.66,3765.62 h30
  text "Slot" at 7632.6,3765.62 h30
  text "Top Layer - Bottom Layer" at 8015.5,3765.62 h30
  text "162.00mil (4.115mm)" at 9332.12,3765.62 h30
  text "2" at 6339.94,3690.62 h30
  text "23.62mil (0.600mm)" at 6674.85,3690.62 h30
  text "PTH" at 7363.66,3690.62 h30
  text "Slot" at 7632.6,3690.62 h30
  text "Top Layer - Bottom Layer" at 8015.5,3690.62 h30
  text "51.18mil (1.300mm)" at 9332.12,3690.62 h30
  text "407 Total" at 6339.94,3615.62 h30
  text "Slot definitions :" at 6071,3533.14 h30
  text "Routed Path Length" at 6601.34,3533.14 h30
  text "= Calculated from tool start centre position to tool end centre position." at 7166.68,3533.14 h30
  text "Hole Length" at 6601.34,3473.15 h30
  text "= Routed Path Length + Tool Size = Slot length as defined in the PCB layout" at 6961.74,3473.15 h30
  text ".Layer_Name" at 527,-1523.49 h30
M17 Embedded Cavity:
  text ".Layer_Name" at 527,-1523.49 h30
M18 Embedded Assembly:
  text ".Layer_Name" at 527,-1523.49 h30
M19 Embedded Keepout:
  text ".Layer_Name" at 527,-1523.49 h30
